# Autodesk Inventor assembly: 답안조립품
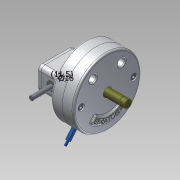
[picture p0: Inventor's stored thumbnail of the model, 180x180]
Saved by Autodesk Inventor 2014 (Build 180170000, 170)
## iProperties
Created: 2015-04
Part Number: 답안조립품
Document SubType Name: Assembly
Designer: Administrator
Author: Administrator
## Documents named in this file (15)
- C:\Documents and Settings\Administrator\바탕 화면\350406V1043\답안조립품.iam
- C:\Documents and Settings\Administrator\바탕 화면\350406V1043\스프링.ipt
- C:\Documents and Settings\Administrator\바탕 화면\350406V1043\본체.ipt
- C:\Documents and Settings\Administrator\바탕 화면\350406V1043\커버.ipt
- C:\Documents and Settings\Administrator\바탕 화면\350406V1043\커버2.ipt
- C:\Documents and Settings\Administrator\바탕 화면\350406V1043\M 10 x 35.ipt
- C:\Documents and Settings\Administrator\바탕 화면\350406V1043\M 5 x 12.ipt
- C:\Documents and Settings\Administrator\바탕 화면\350406V1043\부시.ipt
- C:\Documents and Settings\Administrator\바탕 화면\350406V1043\슬라이더3.ipt
- C:\Documents and Settings\Administrator\바탕 화면\350406V1043\축.ipt
- C:\Documents and Settings\Administrator\바탕 화면\350406V1043\베어링62_22.ipt
- C:\Documents and Settings\Administrator\바탕 화면\350406V1043\멈춤링.ipt
- C:\Documents and Settings\Administrator\바탕 화면\350406V1043\슬라이더2.ipt
- C:\Documents and Settings\Administrator\바탕 화면\350406V1043\평행핀.ipt
- C:\Documents and Settings\Administrator\바탕 화면\350406V1043\슬라이더.ipt
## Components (5 placed, 3 different names)
1. M 10 x 35:1
2. M 10 x 35:2
3. M 5 x 12:1
4. M 5 x 12:2
5. KS B 1320 B B 5 x  20:1 — 플러쉬:1
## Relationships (1: Flush 1)
- 플러쉬:1 [Flush]: KS B 1320 B B 5 x  20:1
